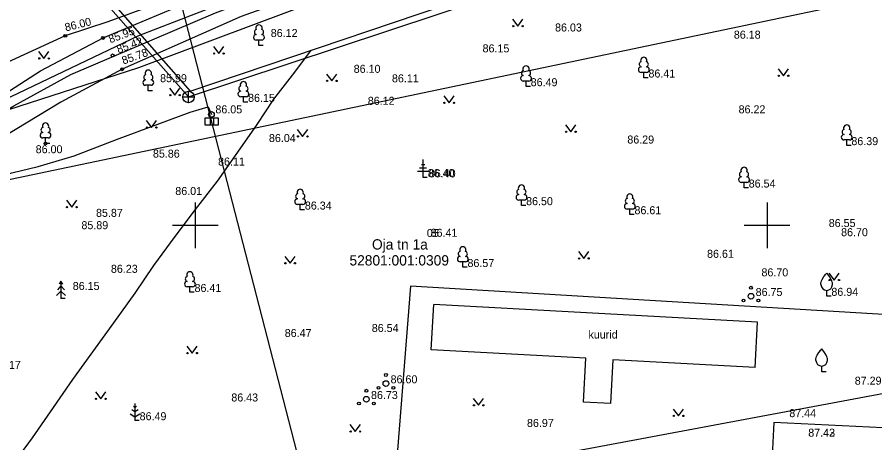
# Model space of a CAD drawing. Extents: x 648748 to 649126, y 6457789 to 6458252.
# Drawn here: x 648884.4 to 648959.4, y 6458081 to 6458118.2 of the extents above; entities that cross this region are included whole.
import ezdxf

# ---------------------------------------------------------------- set-up
doc = ezdxf.new("R2010")
doc.units = 0
for name, color, linetype in [('ELRAJATISMP', 7, 'Continuous'), ('HALJASTUS', 7, 'Continuous'), ('KKAEV', 7, 'Continuous'), ('KORGUS-EH2000', 7, 'Continuous'), ('KTRASS', 7, 'Continuous'), ('MPKAABEL', 7, 'Continuous'), ('MPOHULIIN', 7, 'Continuous'), ('PIIR', 7, 'Continuous'), ('POST', 7, 'Continuous'), ('PUU', 7, 'Continuous'), ('RAJATIS', 7, 'Continuous'), ('SITRASS', 7, 'Continuous'), ('SKTRASS', 7, 'Continuous'), ('TEE', 7, 'Continuous'), ('VEEKOGU', 7, 'Continuous'), ('VORK', 7, 'Continuous'), ('VTRASS', 7, 'Continuous')]:
    doc.layers.add(name, color=color, linetype=linetype)

msp = doc.modelspace()

# ---------------------------------------------------------------- linework, layer by layer
at = {"layer": 'ELRAJATISMP'}
for p, q in [((648902.046, 6458109.371), (648900.851, 6458109.371)), ((648900.851, 6458109.371), (648900.851, 6458108.774)), ((648901.313, 6458109.371), (648901.313, 6458108.774)), ((648901.584, 6458109.371), (648901.584, 6458108.774)), ((648902.046, 6458108.774), (648902.046, 6458109.371)), ((648900.851, 6458108.774), (648902.046, 6458108.774))]:
    msp.add_line(p, q, dxfattribs=at)
at = {"layer": 'HALJASTUS'}
for p, q in [((648927.747, 6458118.028), (648928.211, 6458117.422)), ((648928.211, 6458117.422), (648928.656, 6458118.028)), ((648886.302, 6458115.203), (648886.765, 6458114.597)), ((648886.765, 6458114.597), (648887.211, 6458115.203)), ((648901.592, 6458115.631), (648902.056, 6458115.024)), ((648902.056, 6458115.024), (648902.501, 6458115.631)), ((648950.962, 6458113.688), (648951.426, 6458113.082)), ((648951.426, 6458113.082), (648951.871, 6458113.688)), ((648911.473, 6458113.233), (648911.937, 6458112.627)), ((648911.937, 6458112.627), (648912.382, 6458113.233)), ((648897.749, 6458111.993), (648898.213, 6458111.386)), ((648898.213, 6458111.386), (648898.658, 6458111.993)), ((648921.727, 6458111.322), (648922.19, 6458110.715)), ((648922.19, 6458110.715), (648922.636, 6458111.322)), ((648895.708, 6458109.165), (648896.171, 6458108.558)), ((648896.171, 6458108.558), (648896.617, 6458109.165)), ((648908.924, 6458108.384), (648909.387, 6458107.778)), ((648909.387, 6458107.778), (648909.833, 6458108.384)), ((648932.369, 6458108.792), (648932.833, 6458108.186)), ((648932.833, 6458108.186), (648933.278, 6458108.792)), ((648888.733, 6458102.19), (648889.196, 6458101.584)), ((648889.196, 6458101.584), (648889.642, 6458102.19)), ((648907.823, 6458097.287), (648908.286, 6458096.681)), ((648908.286, 6458096.681), (648908.732, 6458097.287)), ((648933.511, 6458097.716), (648933.974, 6458097.109)), ((648933.974, 6458097.109), (648934.42, 6458097.716)), ((648955.407, 6458095.821), (648955.87, 6458095.215)), ((648955.87, 6458095.215), (648956.316, 6458095.821)), ((648899.26, 6458089.434), (648899.724, 6458088.827)), ((648899.724, 6458088.827), (648900.169, 6458089.434)), ((648891.268, 6458085.436), (648891.732, 6458084.829)), ((648891.732, 6458084.829), (648892.177, 6458085.436)), ((648924.306, 6458084.865), (648924.769, 6458084.258)), ((648924.769, 6458084.258), (648925.215, 6458084.865)), ((648941.788, 6458083.936), (648942.251, 6458083.33)), ((648942.251, 6458083.33), (648942.697, 6458083.936)), ((648913.531, 6458082.58), (648913.995, 6458081.973)), ((648913.995, 6458081.973), (648914.44, 6458082.58))]:
    msp.add_line(p, q, dxfattribs=at)
for centre in [(648927.81, 6458117.422), (648928.639, 6458117.422), (648886.364, 6458114.597), (648887.193, 6458114.597), (648901.655, 6458115.024), (648902.484, 6458115.024), (648951.025, 6458113.082), (648951.854, 6458113.082), (648911.536, 6458112.627), (648912.365, 6458112.627), (648897.812, 6458111.386), (648898.641, 6458111.386), (648921.789, 6458110.715), (648922.618, 6458110.715), (648895.77, 6458108.558), (648896.599, 6458108.558), (648908.986, 6458107.778), (648909.815, 6458107.778), (648932.432, 6458108.186), (648933.261, 6458108.186), (648888.795, 6458101.584), (648889.624, 6458101.584), (648933.573, 6458097.109), (648934.402, 6458097.109), (648907.885, 6458096.681), (648908.714, 6458096.681), (648955.469, 6458095.215), (648956.298, 6458095.215), (648899.323, 6458088.827), (648900.152, 6458088.827), (648891.331, 6458084.829), (648892.16, 6458084.829), (648924.368, 6458084.258), (648925.197, 6458084.258), (648941.85, 6458083.33), (648942.679, 6458083.33), (648913.594, 6458081.973), (648914.423, 6458081.973)]:
    msp.add_circle(centre, 0.055, dxfattribs=at)
at = {"layer": 'KKAEV'}
for p, q in [((648899.409, 6458110.726), (648899.409, 6458111.726)), ((648898.909, 6458111.226), (648899.909, 6458111.226))]:
    msp.add_line(p, q, dxfattribs=at)
msp.add_circle((648899.409, 6458111.226), 0.5, dxfattribs=at)
at = {"layer": 'KORGUS-EH2000'}
for centre in [(648888.636, 6458116.575), (648891.938, 6458116.388), (648892.775, 6458114.862), (648893.604, 6458113.65), (648886.911, 6458107.166)]:
    msp.add_circle(centre, 0.125, dxfattribs=at)
at = {"layer": 'KTRASS'}
for p, q in [((648887.002, 6458125.324), (648899.409, 6458111.226)), ((648899.409, 6458111.226), (648928.625, 6458120.93))]:
    msp.add_line(p, q, dxfattribs=at)
at = {"layer": 'MPKAABEL'}
msp.add_lwpolyline([(648878.132, 6458103.308), (648879.432, 6458103.446), (648881.405, 6458103.864), (648883.958, 6458104.599), (648886.258, 6458105.149), (648889.402, 6458106.07), (648893.112, 6458107.492), (648899.554, 6458109.896), (648901.121, 6458110.372), (648901.414, 6458109.695)], dxfattribs=at)
at = {"layer": 'MPOHULIIN'}
msp.add_line((648964.567, 6458086.1), (648917.398, 6458077.299), dxfattribs=at)
msp.add_lwpolyline([(648879.733, 6458193.241), (648887.677, 6458162.414), (648896.676, 6458127.492), (648901.112, 6458110.279), (648910.288, 6458074.678)], dxfattribs=at)
at = {"layer": 'PIIR'}
for p, q in [((648895.06, 6458113.79), (648952.09, 6458135.31)), ((648874.11, 6458107.05), (648895.06, 6458113.79)), ((648918.81, 6458094.69), (648916.97, 6458071.27)), ((648965.52, 6458091.89), (648918.81, 6458094.69))]:
    msp.add_line(p, q, dxfattribs=at)
at = {"layer": 'POST'}
msp.add_circle((648901.414, 6458109.695), 0.25, dxfattribs=at)
at = {"layer": 'PUU'}
for p, q in [((648905.811, 6458116.2), (648905.331, 6458116.2)), ((648905.571, 6458115.725), (648905.571, 6458116.2)), ((648905.951, 6458115.725), (648905.571, 6458115.725)), ((648939.462, 6458113.379), (648938.982, 6458113.379)), ((648939.222, 6458112.904), (648939.222, 6458113.379)), ((648939.602, 6458112.904), (648939.222, 6458112.904)), ((648896.135, 6458112.25), (648895.655, 6458112.25)), ((648895.895, 6458111.775), (648895.895, 6458112.25)), ((648929.163, 6458112.618), (648928.683, 6458112.618)), ((648928.923, 6458112.143), (648928.923, 6458112.618)), ((648929.303, 6458112.143), (648928.923, 6458112.143)), ((648896.275, 6458111.775), (648895.895, 6458111.775)), ((648904.452, 6458111.248), (648903.972, 6458111.248)), ((648904.212, 6458110.773), (648904.212, 6458111.248)), ((648904.592, 6458110.773), (648904.212, 6458110.773)), ((648887.151, 6458107.641), (648886.671, 6458107.641)), ((648886.911, 6458107.166), (648886.911, 6458107.641)), ((648887.291, 6458107.166), (648886.911, 6458107.166)), ((648957.205, 6458107.464), (648956.725, 6458107.464)), ((648956.965, 6458106.989), (648956.965, 6458107.464)), ((648957.345, 6458106.989), (648956.965, 6458106.989)), ((648919.92, 6458104.195), (648919.92, 6458105.77)), ((648920.42, 6458104.695), (648919.42, 6458104.695)), ((648920.22, 6458104.995), (648919.62, 6458104.995)), ((648920.07, 6458105.295), (648919.77, 6458105.295)), ((648920.28, 6458104.195), (648919.92, 6458104.195)), ((648948.228, 6458103.755), (648947.748, 6458103.755)), ((648947.988, 6458103.28), (648947.988, 6458103.755)), ((648948.368, 6458103.28), (648947.988, 6458103.28)), ((648909.419, 6458101.83), (648908.939, 6458101.83)), ((648909.179, 6458101.355), (648909.179, 6458101.83)), ((648928.763, 6458102.214), (648928.283, 6458102.214)), ((648928.523, 6458101.739), (648928.523, 6458102.214)), ((648928.903, 6458101.739), (648928.523, 6458101.739)), ((648909.559, 6458101.355), (648909.179, 6458101.355)), ((648938.24, 6458101.421), (648937.76, 6458101.421)), ((648938, 6458100.946), (648938, 6458101.421)), ((648938.38, 6458100.946), (648938, 6458100.946)), ((648923.636, 6458096.804), (648923.156, 6458096.804)), ((648923.396, 6458096.329), (648923.396, 6458096.804)), ((648923.776, 6458096.329), (648923.396, 6458096.329)), ((648888.258, 6458095.105), (648888.108, 6458094.855)), ((648888.408, 6458094.855), (648888.258, 6458095.105)), ((648888.258, 6458095.105), (648888.258, 6458093.605)), ((648888.258, 6458094.255), (648887.858, 6458093.855)), ((648888.258, 6458094.705), (648887.958, 6458094.355)), ((648888.558, 6458094.355), (648888.258, 6458094.705)), ((648888.658, 6458093.855), (648888.258, 6458094.255)), ((648899.772, 6458094.623), (648899.292, 6458094.623)), ((648899.532, 6458094.148), (648899.532, 6458094.623)), ((648899.912, 6458094.148), (648899.532, 6458094.148)), ((648955.216, 6458093.81), (648955.216, 6458094.31)), ((648888.618, 6458093.605), (648888.258, 6458093.605)), ((648955.616, 6458093.81), (648955.216, 6458093.81)), ((648954.778, 6458087.189), (648954.778, 6458087.689)), ((648955.178, 6458087.189), (648954.778, 6458087.189)), ((648894.73, 6458084.431), (648894.73, 6458082.931)), ((648894.73, 6458083.681), (648894.464, 6458083.859)), ((648894.73, 6458084.081), (648894.605, 6458084.164)), ((648894.855, 6458084.164), (648894.73, 6458084.081)), ((648894.997, 6458083.859), (648894.73, 6458083.681)), ((648894.306, 6458083.521), (648894.73, 6458083.237)), ((648894.73, 6458083.237), (648895.155, 6458083.521)), ((648895.09, 6458082.931), (648894.73, 6458082.931))]:
    msp.add_line(p, q, dxfattribs=at)
for points in [[(648954.716, 6458094.81), (648954.716, 6458094.96), (648954.726, 6458095.025), (648954.761, 6458095.155), (648954.821, 6458095.275), (648954.966, 6458095.51), (648955.126, 6458095.715), (648955.216, 6458095.81)], [(648955.716, 6458094.81), (648955.716, 6458094.96), (648955.706, 6458095.025), (648955.671, 6458095.155), (648955.611, 6458095.275), (648955.466, 6458095.51), (648955.306, 6458095.715), (648955.216, 6458095.81)], [(648954.278, 6458088.189), (648954.278, 6458088.339), (648954.288, 6458088.404), (648954.323, 6458088.534), (648954.383, 6458088.654), (648954.528, 6458088.889), (648954.688, 6458089.094), (648954.778, 6458089.189)], [(648955.278, 6458088.189), (648955.278, 6458088.339), (648955.268, 6458088.404), (648955.233, 6458088.534), (648955.173, 6458088.654), (648955.028, 6458088.889), (648954.868, 6458089.094), (648954.778, 6458089.189)]]:
    msp.add_lwpolyline(points, dxfattribs=at)
for centre, radius in [((648948.594, 6458094.546), 0.125), ((648947.944, 6458093.421), 0.125), ((648948.594, 6458093.796), 0.25), ((648949.244, 6458093.421), 0.125), ((648916.674, 6458086.91), 0.125), ((648916.024, 6458085.785), 0.125), ((648916.674, 6458086.16), 0.25), ((648917.324, 6458085.785), 0.125), ((648914.961, 6458085.537), 0.125), ((648914.311, 6458084.412), 0.125), ((648914.961, 6458084.787), 0.25), ((648915.611, 6458084.412), 0.125)]:
    msp.add_circle(centre, radius, dxfattribs=at)
for centre, radius, start, end in [((648905.571, 6458117.245), 0.277, 332.58, 207.42), ((648905.334, 6458116.438), 0.238, 90.002, 269.395), ((648905.401, 6458116.898), 0.233, 109.022, 253.142), ((648905.741, 6458116.898), 0.233, 286.851, 70.986), ((648905.809, 6458116.438), 0.238, 270.605, 89.998), ((648939.222, 6458114.424), 0.277, 332.58, 207.42), ((648928.923, 6458113.663), 0.277, 332.58, 207.42), ((648938.985, 6458113.616), 0.238, 90.002, 269.395), ((648939.052, 6458114.076), 0.233, 109.022, 253.142), ((648939.392, 6458114.076), 0.233, 286.851, 70.986), ((648939.459, 6458113.616), 0.238, 270.605, 89.998), ((648895.725, 6458112.948), 0.233, 109.022, 253.142), ((648895.895, 6458113.295), 0.277, 332.58, 207.42), ((648896.065, 6458112.948), 0.233, 286.851, 70.986), ((648928.685, 6458112.856), 0.238, 90.002, 269.395), ((648928.753, 6458113.316), 0.233, 109.022, 253.142), ((648929.093, 6458113.316), 0.233, 286.851, 70.986), ((648929.16, 6458112.856), 0.238, 270.605, 89.998), ((648895.658, 6458112.488), 0.238, 90.002, 269.395), ((648896.133, 6458112.488), 0.238, 270.605, 89.998), ((648904.042, 6458111.946), 0.233, 109.022, 253.142), ((648904.212, 6458112.293), 0.277, 332.58, 207.42), ((648904.382, 6458111.946), 0.233, 286.851, 70.986), ((648903.975, 6458111.486), 0.238, 90.002, 269.395), ((648904.45, 6458111.486), 0.238, 270.605, 89.998), ((648886.741, 6458108.338), 0.233, 109.022, 253.142), ((648886.911, 6458108.686), 0.277, 332.58, 207.42), ((648887.081, 6458108.338), 0.233, 286.851, 70.986), ((648956.795, 6458108.161), 0.233, 109.022, 253.142), ((648956.965, 6458108.509), 0.277, 332.58, 207.42), ((648957.135, 6458108.161), 0.233, 286.851, 70.986), ((648886.674, 6458107.878), 0.238, 90.002, 269.395), ((648887.149, 6458107.878), 0.238, 270.605, 89.998), ((648956.728, 6458107.701), 0.238, 90.002, 269.395), ((648957.203, 6458107.701), 0.238, 270.605, 89.998), ((648947.818, 6458104.453), 0.233, 109.022, 253.142), ((648947.988, 6458104.8), 0.277, 332.58, 207.42), ((648948.158, 6458104.453), 0.233, 286.851, 70.986), ((648947.751, 6458103.992), 0.238, 90.002, 269.395), ((648948.226, 6458103.992), 0.238, 270.605, 89.998), ((648909.179, 6458102.875), 0.277, 332.58, 207.42), ((648928.353, 6458102.911), 0.233, 109.022, 253.142), ((648928.523, 6458103.259), 0.277, 332.58, 207.42), ((648928.693, 6458102.911), 0.233, 286.851, 70.986), ((648909.009, 6458102.528), 0.233, 109.022, 253.142), ((648909.349, 6458102.528), 0.233, 286.851, 70.986), ((648928.286, 6458102.451), 0.238, 90.002, 269.395), ((648928.761, 6458102.451), 0.238, 270.605, 89.998), ((648938, 6458102.466), 0.277, 332.58, 207.42), ((648908.941, 6458102.068), 0.238, 90.002, 269.395), ((648909.417, 6458102.068), 0.238, 270.605, 89.998), ((648937.763, 6458101.659), 0.238, 90.002, 269.395), ((648937.83, 6458102.119), 0.233, 109.022, 253.142), ((648938.17, 6458102.119), 0.233, 286.851, 70.986), ((648938.238, 6458101.659), 0.238, 270.605, 89.998), ((648923.396, 6458097.849), 0.277, 332.58, 207.42), ((648923.158, 6458097.042), 0.238, 90.002, 269.395), ((648923.226, 6458097.502), 0.233, 109.022, 253.142), ((648923.566, 6458097.502), 0.233, 286.851, 70.986), ((648923.633, 6458097.042), 0.238, 270.605, 89.998), ((648899.532, 6458095.668), 0.277, 332.58, 207.42), ((648899.295, 6458094.861), 0.238, 90.002, 269.395), ((648899.362, 6458095.321), 0.233, 109.022, 253.142), ((648899.702, 6458095.321), 0.233, 286.851, 70.986), ((648899.77, 6458094.861), 0.238, 270.605, 89.998), ((648955.216, 6458094.81), 0.5, 180, 0), ((648954.778, 6458088.189), 0.5, 180, 0)]:
    msp.add_arc(centre, radius, start, end, dxfattribs=at)
at = {"layer": 'RAJATIS'}
for p, q in [((648920.632, 6458089.109), (648920.848, 6458093.08)), ((648948.945, 6458087.57), (648949.161, 6458091.541)), ((648934.145, 6458088.374), (648920.632, 6458089.109)), ((648933.937, 6458084.545), (648934.145, 6458088.374)), ((648936.508, 6458088.246), (648936.3, 6458084.417)), ((648948.945, 6458087.57), (648936.508, 6458088.246)), ((648936.3, 6458084.417), (648933.937, 6458084.545))]:
    msp.add_line(p, q, dxfattribs=at)
msp.add_lwpolyline([(648949.161, 6458091.541), (648920.848, 6458093.08)], dxfattribs=at)
at = {"layer": 'SITRASS'}
msp.add_line((648876.861, 6458102.566), (648968.579, 6458121.81), dxfattribs=at)
msp.add_lwpolyline([(648863.975, 6458121.708), (648868.963, 6458118.276), (648873.908, 6458114.787), (648879.921, 6458111.046), (648881.11, 6458110.63), (648883.242, 6458110.955), (648895.055, 6458116.596), (648901.713, 6458119.167), (648915.597, 6458124.69), (648933.55, 6458131.654), (648947.17, 6458136.394), (648958.488, 6458140.137), (648967.592, 6458140.769)], dxfattribs=at)
at = {"layer": 'SKTRASS'}
msp.add_lwpolyline([(648864.925, 6458092.31), (648866.693, 6458094.618), (648870.108, 6458099.799), (648873.651, 6458103.509), (648877.881, 6458106.787), (648884.142, 6458110.459), (648889.114, 6458113.182), (648901.758, 6458118.582), (648914.292, 6458123.291), (648928.272, 6458129.024), (648937.137, 6458131.944), (648947.113, 6458135.218)], dxfattribs=at)
at = {"layer": 'TEE'}
for points in [[(648964.651, 6458078.174), (648966.451, 6458083.821), (648967.5, 6458089.655), (648970.461, 6458102.422), (648972.022, 6458109.308), (648974.38, 6458121.59), (648976.218, 6458132.059), (648976.233, 6458135.434), (648975.702, 6458138.304), (648974.226, 6458140.713), (648971.86, 6458143.333), (648969.445, 6458145.153), (648966.422, 6458144.919), (648958.871, 6458143.041), (648949.896, 6458140.146), (648946.296, 6458138.815), (648935.488, 6458134.684), (648924.063, 6458130.013), (648903.056, 6458121.74), (648892.363, 6458117.796), (648888.636, 6458116.575), (648879.911, 6458112.582)], [(648962.555, 6458082.165), (648950.584, 6458082.755), (648950.441, 6458079.851), (648956.296, 6458079.563)]]:
    msp.add_lwpolyline(points, dxfattribs=at)
at = {"layer": 'VEEKOGU'}
msp.add_lwpolyline([(648881.501, 6458110.34), (648886.47, 6458113.521), (648891.938, 6458116.388), (648903.218, 6458121.14), (648912.855, 6458125.083), (648924.425, 6458129.317), (648935.909, 6458133.554), (648937.278, 6458129.638), (648925.712, 6458126.147), (648913.923, 6458121.814), (648904.01, 6458118.277), (648893.604, 6458113.65), (648888.243, 6458110.763), (648882.29, 6458107.188)], dxfattribs=at)
at = {"layer": 'VORK'}
for p, q in [((648900, 6458102), (648900, 6458098)), ((648950, 6458102), (648950, 6458098)), ((648898, 6458100), (648902, 6458100)), ((648948, 6458100), (648952, 6458100))]:
    msp.add_line(p, q, dxfattribs=at)
at = {"layer": 'VTRASS'}
for points in [[(648859.612, 6458137.039), (648866.748, 6458133.902), (648887.357, 6458125.656), (648899.553, 6458111.732), (648928.544, 6458121.558), (648956.932, 6458132.595), (648957.558, 6458132.798), (648975.434, 6458138.594), (648975.797, 6458138.798), (648976.302, 6458139.082)], [(648910.103, 6458115.308), (648909.913, 6458115.04), (648908.47, 6458113.137), (648906.851, 6458111.036), (648905.372, 6458108.811), (648903.692, 6458106.391), (648901.924, 6458103.862), (648900, 6458101.379), (648898.201, 6458099.032), (648896.341, 6458096.492), (648894.707, 6458094.076), (648892.853, 6458091.484), (648889.257, 6458086.508), (648887.3, 6458083.687), (648885.726, 6458081.404), (648883.963, 6458079.005)]]:
    msp.add_lwpolyline(points, dxfattribs=at)

# ---------------------------------------------------------------- texts
at = {"layer": 'KORGUS-EH2000'}
for s, rotation, p in [('86.00', 13.80279, (648888.688, 6458116.954)), ('85.95', 20.08529, (648892.573, 6458115.918)), ('85.42', 20.08529, (648893.282, 6458115.025)), ('85.78', 19.55946, (648893.728, 6458114.053))]:
    msp.add_text(s, height=0.7, rotation=rotation, dxfattribs=at).set_placement(p)
for s, p in [('86.03', (648931.462, 6458116.952)), ('86.12', (648906.603, 6458116.467)), ('86.18', (648947.095, 6458116.324)), ('86.15', (648925.124, 6458115.125)), ('86.10', (648913.856, 6458113.336)), ('86.41', (648939.629, 6458112.927)), ('85.99', (648896.927, 6458112.517)), ('86.11', (648917.199, 6458112.505)), ('86.49', (648929.33, 6458112.166)), ('86.15', (648904.619, 6458110.796)), ('86.12', (648915.088, 6458110.538)), ('86.05', (648901.761, 6458109.792)), ('86.22', (648947.511, 6458109.795)), ('86.04', (648906.444, 6458107.285)), ('86.29', (648937.782, 6458107.152)), ('86.39', (648957.372, 6458107.012)), ('86.00', (648886.048, 6458106.305)), ('85.86', (648896.299, 6458105.92)), ('86.11', (648901.993, 6458105.227)), ('86.40', (648920.327, 6458104.218)), ('86.40', (648920.424, 6458104.189)), ('86.54', (648948.395, 6458103.303)), ('86.01', (648898.256, 6458102.652)), ('86.50', (648928.93, 6458101.762)), ('86.34', (648909.586, 6458101.378)), ('86.61', (648938.407, 6458100.969)), ('85.87', (648891.324, 6458100.74)), ('85.89', (648890.047, 6458099.662)), ('86.55', (648955.392, 6458099.85)), ('05 ', (648920.248, 6458098.975)), ('86.41', (648920.58, 6458098.998)), ('86.70', (648956.474, 6458099.048)), ('86.61', (648944.753, 6458097.159)), ('86.23', (648892.626, 6458095.846)), ('86.57', (648923.803, 6458096.352)), ('86.70', (648949.51, 6458095.537)), ('86.15', (648889.29, 6458094.347)), ('86.41', (648899.939, 6458094.171)), ('86.75', (648949.001, 6458093.819)), ('86.94', (648955.623, 6458093.833)), ('86.54', (648915.437, 6458090.671)), ('86.47', (648907.825, 6458090.232)), ('86.17', (648882.402, 6458087.442)), ('86.60', (648917.081, 6458086.183)), ('87.29', (648957.665, 6458086.063)), ('86.43', (648903.155, 6458084.594)), ('86.73', (648915.368, 6458084.81)), ('86.49', (648895.137, 6458082.954)), ('87.44', (648951.946, 6458083.222)), ('86.97', (648929.007, 6458082.366)), ('87.42', (648953.598, 6458081.517)), ('87.43', (648953.604, 6458081.519))]:
    msp.add_text(s, height=0.7, dxfattribs=at).set_placement(p)
at = {"layer": 'PIIR'}
for s, p in [('Oja tn 1a', (648915.454, 6458097.883)), ('52801:001:0309', (648913.486, 6458096.487))]:
    msp.add_text(s, height=0.9, dxfattribs=at).set_placement(p)
at = {"layer": 'RAJATIS'}
msp.add_text('kuurid', height=0.7, dxfattribs=at).set_placement((648934.385, 6458090.1))

doc.saveas('drawing.dxf')
